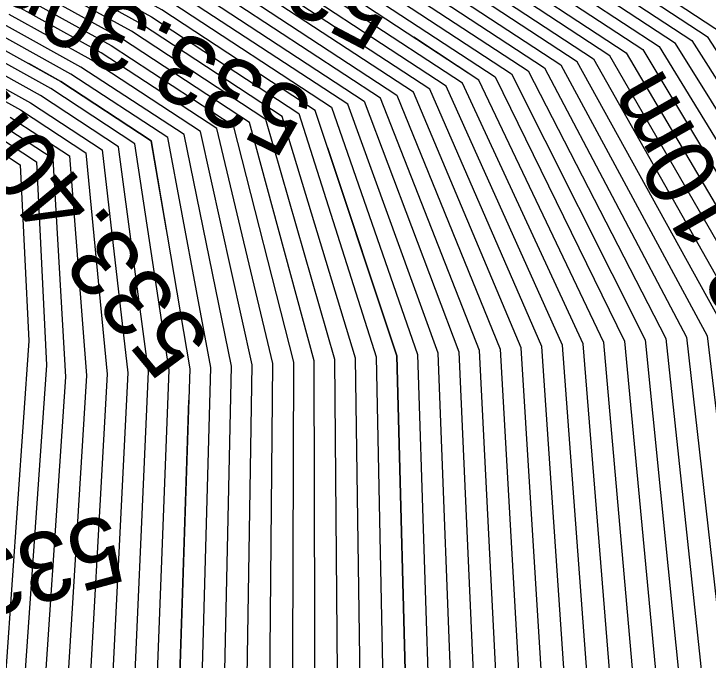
# Model space of a CAD drawing. Extents: x -866683 to -866410, y -1041951 to -1040252.
# Drawn here: x -866449.115 to -866446.097, y -1041928.421 to -1041925.613 of the extents above; entities that cross this region are included whole.
import ezdxf

# ---------------------------------------------------------------- set-up
doc = ezdxf.new("R2010")
doc.units = 0
doc.layers.add('V-VEDL', color=7, linetype='Continuous')
doc.layers.add('V_po_cm', color=7, linetype='Continuous')

msp = doc.modelspace()

# ---------------------------------------------------------------- linework, layer by layer
at = {"layer": 'V-VEDL'}
for points in [[(-866449.7169, -1041924.4172), (-866449.1108, -1041924.2576), (-866448.5043, -1041924.4695), (-866447.5946, -1041924.9732), (-866446.3815, -1041925.7685), (-866445.6512, -1041926.9834), (-866445.4039, -1041928.6176), (-866445.6394, -1041930.6714), (-866445.7539, -1041932.2504), (-866445.7474, -1041933.3549), (-866445.6198, -1041933.9847), (-866446.0907, -1041935.3297), (-866447.16, -1041937.39), (-866450.4954, -1041942.9408)], [(-866450.4284, -1041941.6368), (-866447.8087, -1041937.2771), (-866446.9808, -1041935.6001), (-866446.6348, -1041934.426), (-866446.7708, -1041933.7547), (-866446.7777, -1041932.5775), (-866446.6557, -1041930.8945), (-866446.4047, -1041928.7056), (-866446.5506, -1041927.0409), (-866447.0935, -1041925.9004), (-866448.0334, -1041925.2842), (-866448.7383, -1041924.894), (-866449.2081, -1041924.7298), (-866449.6778, -1041924.8534)], [(-866450.3613, -1041940.3327), (-866448.4574, -1041937.1642), (-866447.8709, -1041935.8705), (-866447.6498, -1041934.8672), (-866447.7942, -1041934.1545), (-866447.8016, -1041932.9046), (-866447.672, -1041931.1176), (-866447.4055, -1041928.7935), (-866447.45, -1041927.0984), (-866447.8056, -1041926.0323), (-866448.4722, -1041925.5952), (-866448.9722, -1041925.3184), (-866449.3055, -1041925.2019), (-866449.6386, -1041925.2896)], [(-866449.5994, -1041925.7259), (-866449.4028, -1041925.6741), (-866449.2061, -1041925.7428), (-866448.9111, -1041925.9062), (-866448.5176, -1041926.1641), (-866448.3494, -1041927.1559), (-866448.4062, -1041928.8814), (-866448.6883, -1041931.3407), (-866448.8254, -1041933.2317), (-866448.8176, -1041934.5543), (-866448.6648, -1041935.3085), (-866448.761, -1041936.1408), (-866449.1061, -1041937.0514), (-866450.2943, -1041939.0287)]]:
    msp.add_lwpolyline(points, dxfattribs=at)
at = {"layer": 'V_po_cm'}
for points in [[(-866449.3993, -1041924.1103), (-866449.0621, -1041924.0215), (-866448.3874, -1041924.2573), (-866447.3752, -1041924.8177), (-866446.0254, -1041925.7026), (-866445.2016, -1041926.9546), (-866444.9035, -1041928.5737), (-866445.1313, -1041930.5598), (-866445.242, -1041932.0869), (-866445.2357, -1041933.155), (-866445.1123, -1041933.7641), (-866445.6456, -1041935.1945), (-866446.8356, -1041937.4464), (-866448.6823, -1041940.5196), (-866449.9551, -1041941.8903)], [(-866449.9596, -1041941.7928), (-866448.7114, -1041940.4488), (-866446.9005, -1041937.4351), (-866445.7346, -1041935.2216), (-866445.2138, -1041933.8082), (-866445.338, -1041933.195), (-866445.3444, -1041932.1196), (-866445.2329, -1041930.5821), (-866445.0036, -1041928.5825), (-866445.2915, -1041926.9604), (-866446.0966, -1041925.7158), (-866447.419, -1041924.8488), (-866448.4108, -1041924.2998), (-866449.0718, -1041924.0688), (-866449.4022, -1041924.1557)], [(-866449.4051, -1041924.2012), (-866449.0816, -1041924.116), (-866448.4342, -1041924.3422), (-866447.4629, -1041924.8799), (-866446.1679, -1041925.729), (-866445.3814, -1041926.9661), (-866445.1037, -1041928.5912), (-866445.3345, -1041930.6044), (-866445.4468, -1041932.1523), (-866445.4404, -1041933.235), (-866445.3153, -1041933.8523), (-866445.8236, -1041935.2486), (-866446.9654, -1041937.4238), (-866448.7404, -1041940.3779), (-866449.964, -1041941.6954)], [(-866449.9684, -1041941.598), (-866448.7695, -1041940.3071), (-866447.0302, -1041937.4125), (-866445.9127, -1041935.2757), (-866445.4168, -1041933.8965), (-866445.5427, -1041933.2749), (-866445.5492, -1041932.185), (-866445.4362, -1041930.6267), (-866445.2037, -1041928.6), (-866445.4714, -1041926.9719), (-866446.2391, -1041925.7422), (-866447.5068, -1041924.911), (-866448.4576, -1041924.3847), (-866449.0913, -1041924.1632), (-866449.408, -1041924.2466)], [(-866449.4109, -1041924.292), (-866449.101, -1041924.2104), (-866448.4809, -1041924.4271), (-866447.5507, -1041924.9421), (-866446.3103, -1041925.7554), (-866445.5613, -1041926.9776), (-866445.3038, -1041928.6088), (-866445.5378, -1041930.649), (-866445.6515, -1041932.2177), (-866445.645, -1041933.3149), (-866445.5183, -1041933.9406), (-866446.0017, -1041935.3027), (-866447.0951, -1041937.4012), (-866448.7986, -1041940.2362), (-866449.9728, -1041941.5006)], [(-866449.1205, -1041924.3048), (-866448.5277, -1041924.512), (-866447.6385, -1041925.0043), (-866446.4527, -1041925.7817), (-866445.7412, -1041926.9891), (-866445.504, -1041928.6264), (-866445.7411, -1041930.6937), (-866445.8563, -1041932.2832), (-866445.8497, -1041933.3949), (-866445.7213, -1041934.0288), (-866446.1797, -1041935.3568), (-866447.2248, -1041937.3787), (-866448.8568, -1041940.0945), (-866449.9816, -1041941.3058)], [(-866449.9861, -1041941.2084), (-866448.8859, -1041940.0237), (-866447.2897, -1041937.3674), (-866446.2687, -1041935.3838), (-866445.8228, -1041934.073), (-866445.9521, -1041933.4349), (-866445.9587, -1041932.3159), (-866445.8427, -1041930.716), (-866445.6041, -1041928.6352), (-866445.8311, -1041926.9949), (-866446.5239, -1041925.7949), (-866447.6823, -1041925.0354), (-866448.5511, -1041924.5544), (-866449.1302, -1041924.352)], [(-866449.14, -1041924.3993), (-866448.5745, -1041924.5969), (-866447.7262, -1041925.0665), (-866446.5951, -1041925.8081), (-866445.9211, -1041927.0006), (-866445.7041, -1041928.644), (-866445.9443, -1041930.7383), (-866446.0611, -1041932.3486), (-866446.0544, -1041933.4748), (-866445.9243, -1041934.1171), (-866446.3577, -1041935.4108), (-866447.3546, -1041937.3561), (-866448.9149, -1041939.9529), (-866449.9905, -1041941.111)], [(-866449.9949, -1041941.0136), (-866448.944, -1041939.882), (-866447.4195, -1041937.3448), (-866446.4467, -1041935.4379), (-866446.0258, -1041934.1612), (-866446.1567, -1041933.5148), (-866446.1634, -1041932.3813), (-866446.0459, -1041930.7606), (-866445.8042, -1041928.6528), (-866446.011, -1041927.0064), (-866446.6663, -1041925.8213), (-866447.7701, -1041925.0976), (-866448.5979, -1041924.6393), (-866449.1497, -1041924.4465)], [(-866449.1594, -1041924.4937), (-866448.6213, -1041924.6818), (-866447.814, -1041925.1287), (-866446.7375, -1041925.8345), (-866446.1009, -1041927.0121), (-866445.9043, -1041928.6616), (-866446.1476, -1041930.7829), (-866446.2658, -1041932.414), (-866446.2591, -1041933.5548), (-866446.1273, -1041934.2053), (-866446.5357, -1041935.4649), (-866447.4843, -1041937.3335), (-866448.9731, -1041939.8112), (-866449.9993, -1041940.9162)], [(-866449.1692, -1041924.5409), (-866448.6447, -1041924.7242), (-866447.8579, -1041925.1598), (-866446.8087, -1041925.8477), (-866446.1909, -1041927.0179), (-866446.0044, -1041928.6704), (-866446.2492, -1041930.8052), (-866446.3682, -1041932.4467), (-866446.3614, -1041933.5948), (-866446.2288, -1041934.2495), (-866446.6247, -1041935.492), (-866447.5492, -1041937.3222), (-866449.0022, -1041939.7403), (-866450.0037, -1041940.8188)], [(-866449.1789, -1041924.5881), (-866448.6681, -1041924.7666), (-866447.9018, -1041925.1909), (-866446.8799, -1041925.8608), (-866446.2808, -1041927.0236), (-866446.1044, -1041928.6792), (-866446.3508, -1041930.8275), (-866446.4706, -1041932.4794), (-866446.4638, -1041933.6348), (-866446.3303, -1041934.2936), (-866446.7138, -1041935.519), (-866447.6141, -1041937.3109), (-866449.0313, -1041939.6695), (-866450.0081, -1041940.7214)], [(-866449.1886, -1041924.6353), (-866448.6915, -1041924.8091), (-866447.9456, -1041925.222), (-866446.9511, -1041925.874), (-866446.3707, -1041927.0294), (-866446.2045, -1041928.688), (-866446.4525, -1041930.8499), (-866446.573, -1041932.5121), (-866446.5661, -1041933.6747), (-866446.4318, -1041934.3377), (-866446.8028, -1041935.546), (-866447.6789, -1041937.2997), (-866449.0604, -1041939.5986), (-866450.0125, -1041940.6239)], [(-866449.1984, -1041924.6826), (-866448.7149, -1041924.8515), (-866447.9895, -1041925.2531), (-866447.0223, -1041925.8872), (-866446.4607, -1041927.0351), (-866446.3046, -1041928.6968), (-866446.5541, -1041930.8722), (-866446.6754, -1041932.5448), (-866446.6684, -1041933.7147), (-866446.5333, -1041934.3818), (-866446.8918, -1041935.5731), (-866447.7438, -1041937.2884), (-866449.0895, -1041939.5278), (-866450.017, -1041940.5265)], [(-866449.1476, -1041939.3861), (-866447.8736, -1041937.2658), (-866447.0698, -1041935.6271), (-866446.7363, -1041934.4701), (-866446.8731, -1041933.7947), (-866446.8801, -1041932.6102), (-866446.7573, -1041930.9168), (-866446.5048, -1041928.7143), (-866446.6406, -1041927.0466), (-866447.1647, -1041925.9136), (-866448.0773, -1041925.3153), (-866448.7617, -1041924.9364), (-866449.2179, -1041924.777)], [(-866449.1767, -1041939.3152), (-866447.9384, -1041937.2545), (-866447.1588, -1041935.6542), (-866446.8378, -1041934.5142), (-866446.9755, -1041933.8347), (-866446.9825, -1041932.6429), (-866446.859, -1041930.9391), (-866446.6048, -1041928.7231), (-866446.7305, -1041927.0524), (-866447.2359, -1041925.9268), (-866448.1212, -1041925.3464), (-866448.7851, -1041924.9789), (-866449.2276, -1041924.8242)], [(-866449.2058, -1041939.2444), (-866448.0033, -1041937.2432), (-866447.2478, -1041935.6812), (-866446.9393, -1041934.5583), (-866447.0778, -1041933.8746), (-866447.0849, -1041932.6757), (-866446.9606, -1041930.9614), (-866446.7049, -1041928.7319), (-866446.8204, -1041927.0581), (-866447.3071, -1041925.94), (-866448.1651, -1041925.3775), (-866448.8085, -1041925.0213), (-866449.2373, -1041924.8714)], [(-866449.2349, -1041939.1736), (-866448.0682, -1041937.2319), (-866447.3368, -1041935.7082), (-866447.0408, -1041934.6025), (-866447.1801, -1041933.9146), (-866447.1873, -1041932.7084), (-866447.0622, -1041930.9837), (-866446.805, -1041928.7407), (-866446.9104, -1041927.0639), (-866447.3783, -1041925.9531), (-866448.2089, -1041925.4086), (-866448.8318, -1041925.0637), (-866449.2471, -1041924.9186)], [(-866449.2568, -1041924.9659), (-866448.8552, -1041925.1062), (-866448.2528, -1041925.4397), (-866447.4496, -1041925.9663), (-866447.0003, -1041927.0696), (-866446.9051, -1041928.7495), (-866447.1639, -1041931.0061), (-866447.2897, -1041932.7411), (-866447.2825, -1041933.9546), (-866447.1423, -1041934.6466), (-866447.4258, -1041935.7353), (-866448.133, -1041937.2207), (-866449.264, -1041939.1027)], [(-866449.293, -1041939.0319), (-866448.1979, -1041937.2094), (-866447.5148, -1041935.7623), (-866447.2438, -1041934.6907), (-866447.3848, -1041933.9946), (-866447.392, -1041932.7738), (-866447.2655, -1041931.0284), (-866447.0051, -1041928.7583), (-866447.0902, -1041927.0754), (-866447.5208, -1041925.9795), (-866448.2967, -1041925.4708), (-866448.8786, -1041925.1486), (-866449.2665, -1041925.0131)], [(-866449.2763, -1041925.0603), (-866448.902, -1041925.1911), (-866448.3406, -1041925.5019), (-866447.592, -1041925.9927), (-866447.1802, -1041927.0811), (-866447.1052, -1041928.7671), (-866447.3671, -1041931.0507), (-866447.4944, -1041932.8065), (-866447.4872, -1041934.0345), (-866447.3453, -1041934.7348), (-866447.6039, -1041935.7894), (-866448.2628, -1041937.1981), (-866449.3221, -1041938.961)], [(-866449.3512, -1041938.8902), (-866448.3277, -1041937.1868), (-866447.6929, -1041935.8164), (-866447.4468, -1041934.779), (-866447.5895, -1041934.0745), (-866447.5968, -1041932.8392), (-866447.4687, -1041931.073), (-866447.2053, -1041928.7759), (-866447.2701, -1041927.0869), (-866447.6632, -1041926.0059), (-866448.3845, -1041925.533), (-866448.9254, -1041925.2335), (-866449.286, -1041925.1075)], [(-866449.2957, -1041925.1547), (-866448.9488, -1041925.276), (-866448.4284, -1041925.5641), (-866447.7344, -1041926.0191), (-866447.3601, -1041927.0926), (-866447.3054, -1041928.7847), (-866447.5704, -1041931.0953), (-866447.6992, -1041932.8719), (-866447.6918, -1041934.1145), (-866447.5483, -1041934.8231), (-866447.7819, -1041935.8434), (-866448.3925, -1041937.1755), (-866449.3803, -1041938.8193)], [(-866449.3152, -1041925.2491), (-866448.9956, -1041925.3608), (-866448.5161, -1041925.6263), (-866447.8768, -1041926.0454), (-866447.5399, -1041927.1041), (-866447.5055, -1041928.8023), (-866447.7736, -1041931.1399), (-866447.904, -1041932.9373), (-866447.8965, -1041934.1945), (-866447.7513, -1041934.9114), (-866447.9599, -1041935.8975), (-866448.5223, -1041937.1529), (-866449.4385, -1041938.6776)], [(-866449.4675, -1041938.6068), (-866448.5872, -1041937.1417), (-866448.0489, -1041935.9245), (-866447.8528, -1041934.9555), (-866447.9989, -1041934.2344), (-866448.0063, -1041932.97), (-866447.8753, -1041931.1622), (-866447.6056, -1041928.8111), (-866447.6299, -1041927.1099), (-866447.948, -1041926.0586), (-866448.56, -1041925.6574), (-866449.019, -1041925.4033), (-866449.3249, -1041925.2964)], [(-866449.4966, -1041938.5359), (-866448.652, -1041937.1304), (-866448.1379, -1041935.9516), (-866447.9543, -1041934.9996), (-866448.1012, -1041934.2744), (-866448.1087, -1041933.0027), (-866447.9769, -1041931.1846), (-866447.7057, -1041928.8199), (-866447.7198, -1041927.1156), (-866448.0192, -1041926.0718), (-866448.6039, -1041925.6885), (-866449.0424, -1041925.4457), (-866449.3347, -1041925.3436)], [(-866449.5257, -1041938.4651), (-866448.7169, -1041937.1191), (-866448.2269, -1041935.9786), (-866448.0558, -1041935.0437), (-866448.2035, -1041934.3144), (-866448.2111, -1041933.0355), (-866448.0785, -1041931.2069), (-866447.8058, -1041928.8287), (-866447.8097, -1041927.1214), (-866448.0904, -1041926.085), (-866448.6478, -1041925.7196), (-866449.0658, -1041925.4882), (-866449.3444, -1041925.3908)], [(-866449.3541, -1041925.438), (-866449.0892, -1041925.5306), (-866448.6917, -1041925.7507), (-866448.1616, -1041926.0982), (-866447.8997, -1041927.1271), (-866447.9059, -1041928.8374), (-866448.1801, -1041931.2292), (-866448.3135, -1041933.0682), (-866448.3059, -1041934.3544), (-866448.1573, -1041935.0879), (-866448.3159, -1041936.0057), (-866448.7818, -1041937.1078), (-866449.5548, -1041938.3943)], [(-866449.5839, -1041938.3234), (-866448.8466, -1041937.0965), (-866448.405, -1041936.0327), (-866448.2588, -1041935.132), (-866448.4082, -1041934.3944), (-866448.4159, -1041933.1009), (-866448.2818, -1041931.2515), (-866448.0059, -1041928.8462), (-866447.9896, -1041927.1329), (-866448.2328, -1041926.1114), (-866448.7355, -1041925.7818), (-866449.1126, -1041925.5731), (-866449.3639, -1041925.4852)], [(-866449.613, -1041938.2526), (-866448.9115, -1041937.0852), (-866448.494, -1041936.0597), (-866448.3603, -1041935.1761), (-866448.5106, -1041934.4343), (-866448.5183, -1041933.1336), (-866448.3834, -1041931.2738), (-866448.106, -1041928.855), (-866448.0795, -1041927.1386), (-866448.304, -1041926.1246), (-866448.7794, -1041925.8129), (-866449.136, -1041925.6155)], [(-866449.642, -1041938.1817), (-866448.9764, -1041937.0739), (-866448.583, -1041936.0868), (-866448.4618, -1041935.2202), (-866448.6129, -1041934.4743), (-866448.6206, -1041933.1663), (-866448.485, -1041931.2961), (-866448.2061, -1041928.8638), (-866448.1695, -1041927.1444), (-866448.3752, -1041926.1377), (-866448.8233, -1041925.844), (-866449.1594, -1041925.6579)], [(-866449.6711, -1041938.1109), (-866449.0413, -1041937.0626), (-866448.672, -1041936.1138), (-866448.5633, -1041935.2644), (-866448.7152, -1041934.5143), (-866448.723, -1041933.199), (-866448.5867, -1041931.3184), (-866448.3062, -1041928.8726), (-866448.2594, -1041927.1501), (-866448.4464, -1041926.1509), (-866448.8672, -1041925.8751), (-866449.1827, -1041925.7004)], [(-866446.5098, -1041929.6225), (-866446.4047, -1041928.7056), (-866446.5506, -1041927.0409), (-866447.0935, -1041925.9004), (-866447.3769, -1041925.7146)], [(-866449.171, -1041937.0401), (-866448.85, -1041936.1679), (-866448.7663, -1041935.3526), (-866448.9199, -1041934.5943), (-866448.9278, -1041933.2644), (-866448.7899, -1041931.3631), (-866448.5063, -1041928.8902), (-866448.4393, -1041927.1616), (-866448.5888, -1041926.1773), (-866448.955, -1041925.9373), (-866449.2295, -1041925.7853)], [(-866449.2359, -1041937.0288), (-866448.939, -1041936.1949), (-866448.8678, -1041935.3967), (-866449.0223, -1041934.6342), (-866449.0302, -1041933.2971), (-866448.8915, -1041931.3854), (-866448.6064, -1041928.899), (-866448.5292, -1041927.1674), (-866448.6601, -1041926.1905), (-866448.9988, -1041925.9684), (-866449.2529, -1041925.8277)], [(-866448.4518, -1041926.552), (-866448.5176, -1041926.1641), (-866448.9111, -1041925.9062), (-866449.0505, -1041925.829)], [(-866449.2763, -1041925.8702), (-866449.0427, -1041925.9995), (-866448.7313, -1041926.2037), (-866448.6192, -1041927.1731), (-866448.7065, -1041928.9078), (-866448.9932, -1041931.4077), (-866449.1325, -1041933.3298)], [(-866449.2997, -1041925.9126), (-866449.0866, -1041926.0306), (-866448.8025, -1041926.2169), (-866448.7091, -1041927.1789), (-866448.8066, -1041928.9166), (-866449.0948, -1041931.43), (-866449.2349, -1041933.3625)], [(-866449.1305, -1041926.0617), (-866448.8737, -1041926.2301), (-866448.799, -1041927.1846), (-866448.9066, -1041928.9254), (-866449.1964, -1041931.4523)], [(-866449.2981, -1041931.4746), (-866449.0067, -1041928.9342), (-866448.889, -1041927.1904), (-866448.9449, -1041926.2432), (-866449.1744, -1041926.0928)], [(-866447.7519, -1041926.1933), (-866447.45, -1041927.0984), (-866447.4055, -1041928.7935), (-866447.5764, -1041930.2839)], [(-866448.6839, -1041931.3027), (-866448.4062, -1041928.8814), (-866448.3539, -1041927.2924)]]:
    msp.add_lwpolyline(points, dxfattribs=at)
for points in [[(-866449.4204, -1041925.9913), (-866449.0161, -1041926.2564), (-866448.9725, -1041927.1401), (-866449.0875, -1041928.775), (-866449.3612, -1041931.161), (-866449.6024, -1041931.9084), (-866449.8112, -1041931.0171), (-866449.9875, -1041928.4872), (-866450.0394, -1041926.8088), (-866449.9666, -1041925.9819), (-866449.7693, -1041926.0066), (-866449.6209, -1041926.0186), (-866449.5215, -1041926.0179)], [(-866449.437, -1041926.0403), (-866449.0873, -1041926.2696), (-866449.0496, -1041927.0339), (-866449.1491, -1041928.4478), (-866449.3857, -1041930.5114), (-866449.5944, -1041931.1578), (-866449.7749, -1041930.387), (-866449.9275, -1041928.1989), (-866449.9723, -1041926.7474), (-866449.9094, -1041926.0322), (-866449.7387, -1041926.0535), (-866449.6104, -1041926.0639), (-866449.5244, -1041926.0633)]]:
    msp.add_lwpolyline(points, close=True, dxfattribs=at)

# ---------------------------------------------------------------- texts
for s, rotation, p in [('533.20m', 152.1754, (-866447.4261, -1041925.5187)), ('533.30m', 153.5533, (-866447.7983, -1041925.9745)), ('533.40m', 129.6267, (-866448.2499, -1041927.031)), ('533.10m', 119.5965, (-866445.5376, -1041927.1958)), ('533.50m', 195.1639, (-866448.6925, -1041927.7813))]:
    msp.add_text(s, height=0.3, rotation=rotation, dxfattribs=at).set_placement(p)

doc.saveas('drawing.dxf')
